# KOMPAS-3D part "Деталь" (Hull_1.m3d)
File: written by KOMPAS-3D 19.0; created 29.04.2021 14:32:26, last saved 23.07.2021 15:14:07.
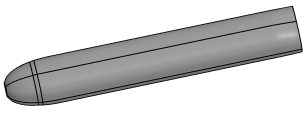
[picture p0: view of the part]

Document properties: Автор: User Windows; Полное имя файла: C:\Hull_1.m3d

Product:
- Part/product: Деталь
    Масса: 38.0727
  - Body: Тело 1
      Масса: 2.32698
  - Body: Тело 2
      Масса: 2.32698

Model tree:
1. Киль
2. Ватерлиния
3. W1
     Расстояние = 4
4. W2
     Расстояние = 6
5. W3
     Расстояние = 5
6. W4
     Расстояние = 5
7. W5
     Расстояние = 10
8. W6
     Расстояние = 10
9. W7
     Расстояние = 10
10. W8
     Расстояние = 10
11. W9
     Расстояние = 10
12. W10
     Расстояние = 10
13. Элемент по сечениям:1
14. W11
     Расстояние = 10
15. W12
     Расстояние = 19
16. W13
     Расстояние = 20
17. W14
     Расстояние = 50
18. W22
     Расстояние = 410
19. W23
     Расстояние = 43
20. W24
     Расстояние = 26
21. W25
     Расстояние = 20
22. W26
     Расстояние = 10
23. Элемент по сечениям:2
24. Эскиз:2  (with: Элемент по сечениям:2)
25. Эскиз:1  (with: Элемент по сечениям:1)
26. Элемент по сечениям:6
27. Элемент по сечениям:5  (with: Элемент по сечениям:2, Элемент по сечениям:1)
